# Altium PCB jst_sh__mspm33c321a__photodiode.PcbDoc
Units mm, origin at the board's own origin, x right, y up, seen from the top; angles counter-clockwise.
Board outline 60 x 34 mm, 2 copper layers (Top, Bottom), stack 0 mm thick; 28 components, 13 nets, 108 pads, 50 vias.
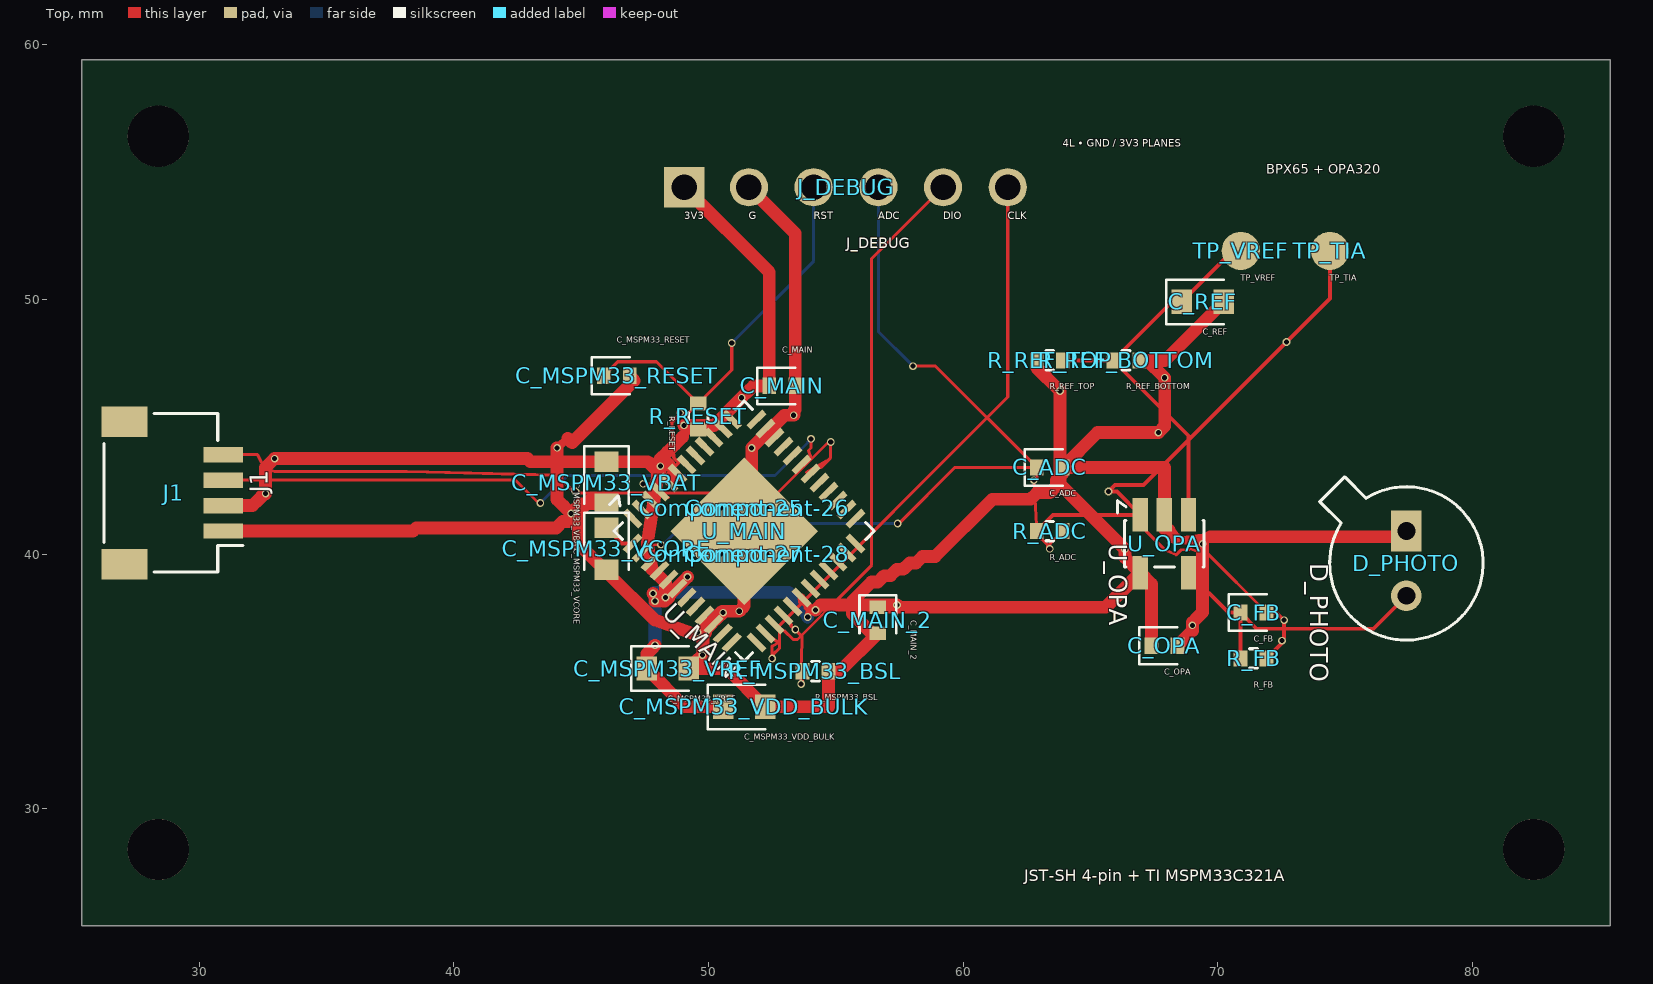
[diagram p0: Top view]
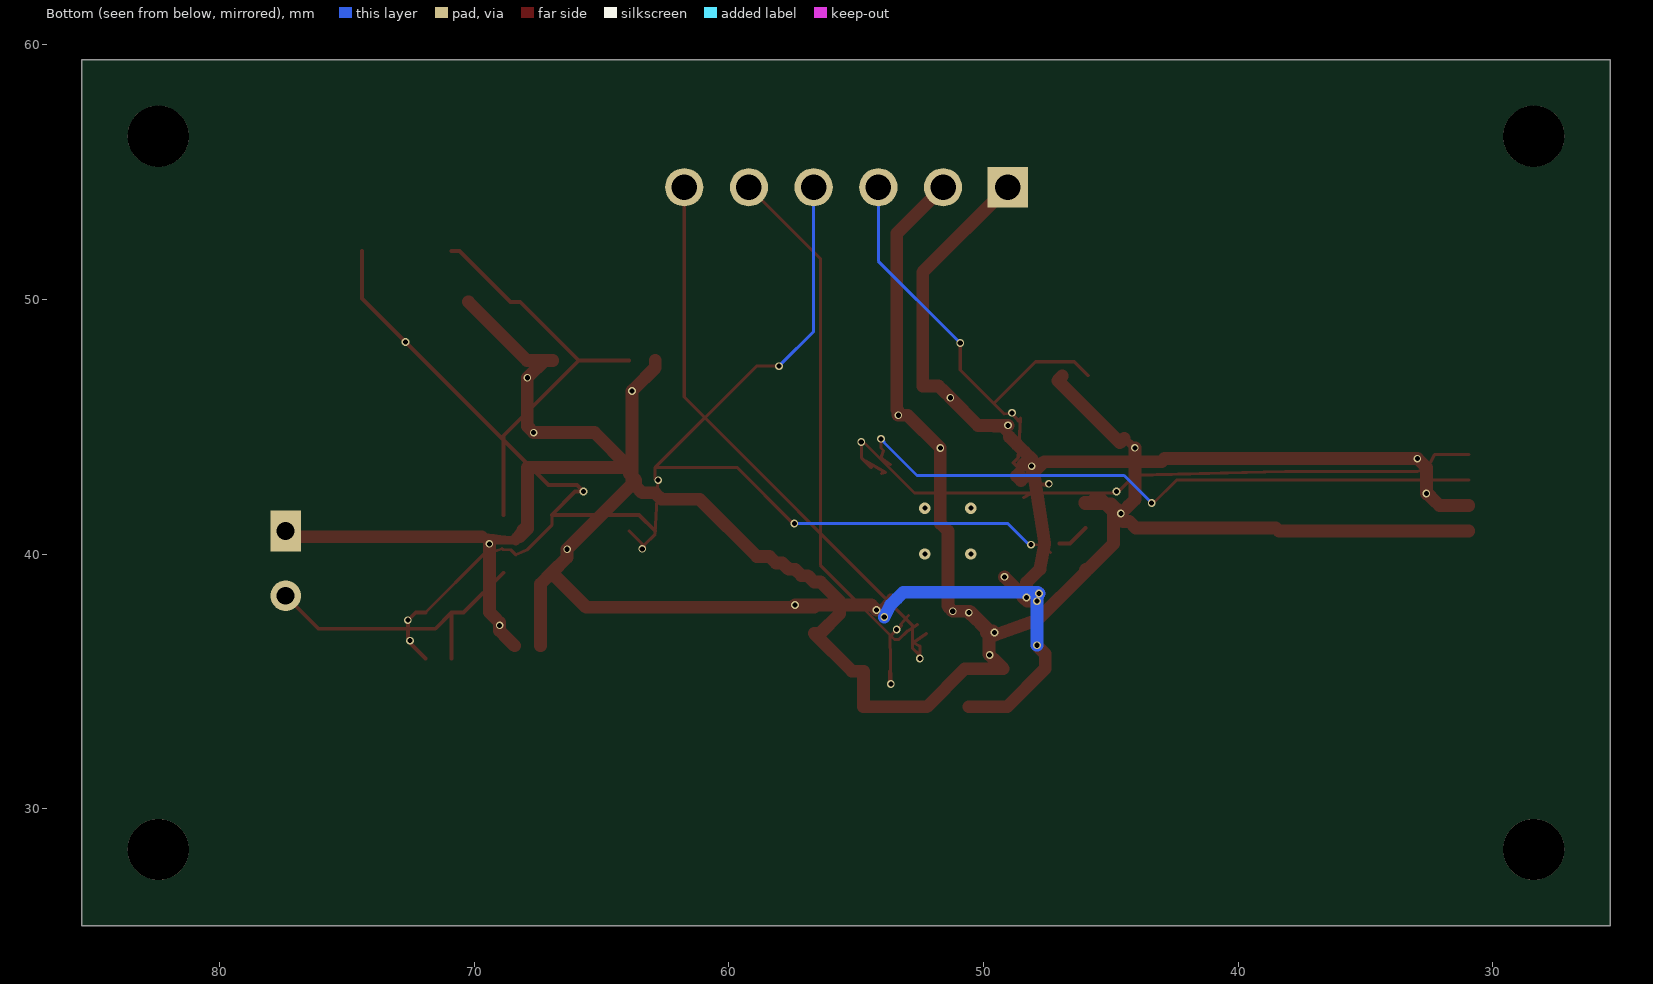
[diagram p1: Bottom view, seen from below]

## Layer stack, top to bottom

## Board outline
25.4,59.4 85.4,59.4 85.4,25.4 25.4,25.4

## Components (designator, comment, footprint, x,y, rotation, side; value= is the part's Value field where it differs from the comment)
C_ADC "" TSCIRCUIT-1.5600x0.6400mm 63.4,43.4 r0 top
C_FB "" TSCIRCUIT-1.5600x0.6400mm 71.4,37.7 r0 top
C_MAIN "" TSCIRCUIT-1.5600x0.6400mm 52.9,46.6 r0 top
C_MAIN_2 "" TSCIRCUIT-0.6400x1.5600mm 56.65,37.4 r270 top
C_MSPM33_RESET "" TSCIRCUIT-1.5600x0.6400mm 46.4,47 r0 top
C_MSPM33_VBAT "" TSCIRCUIT-0.9500x2.4500mm 46,42.8 r270 top
C_MSPM33_VCORE "" TSCIRCUIT-0.9500x2.4500mm 46,40.2 r270 top
C_MSPM33_VDD_BULK "" TSCIRCUIT-2.4500x0.9500mm 51.4,34 r0 top
C_MSPM33_VREF "" TSCIRCUIT-2.4500x0.9500mm 48.4,35.5 r0 top
C_OPA "" TSCIRCUIT-1.5600x0.6400mm 67.9,36.4 r0 top
C_REF "" TSCIRCUIT-2.4500x0.9500mm 69.4,49.9 r0 top
Component-25 "" TSCIRCUIT-0.4500x0.4500mm 50.5,41.8 r0 top
Component-26 "" TSCIRCUIT-0.4500x0.4500mm 52.3,41.8 r0 top
Component-27 "" TSCIRCUIT-0.4500x0.4500mm 50.5,40 r0 top
Component-28 "" TSCIRCUIT-0.4500x0.4500mm 52.3,40 r0 top
D_PHOTO "" TSCIRCUIT-1.2000x3.9400mm 77.4,39.73 r270 top
J1 "" TSCIRCUIT-5.5500x6.8000mm 28.95,42.4 r90 top
J_DEBUG "" TSCIRCUIT-14.2000x1.5000mm 55.4,54.4 r0 top
R_ADC "" TSCIRCUIT-1.5600x0.6400mm 63.4,40.9 r0 top
R_FB "" TSCIRCUIT-1.5600x0.6400mm 71.4,35.9 r0 top
R_MSPM33_BSL "" TSCIRCUIT-1.5600x0.6400mm 54.2,35.4 r0 top
R_REF_BOTTOM "" TSCIRCUIT-1.5600x0.6400mm 66.4,47.6 r0 top
R_REF_TOP "" TSCIRCUIT-1.5600x0.6400mm 63.4,47.6 r0 top
R_RESET "" TSCIRCUIT-0.6400x1.5600mm 49.6,45.4 r270 top
TP_TIA "" TSCIRCUIT-1.5000x1.5000mm 74.4,51.9 r0 top
TP_VREF "" TSCIRCUIT-1.5000x1.5000mm 70.9,51.9 r0 top
U_MAIN "" TSCIRCUIT-9.5459x9.5459mm 51.4,40.9 r315 top
U_OPA "" TSCIRCUIT-2.5000x3.6000mm 67.9,40.4 r270 top

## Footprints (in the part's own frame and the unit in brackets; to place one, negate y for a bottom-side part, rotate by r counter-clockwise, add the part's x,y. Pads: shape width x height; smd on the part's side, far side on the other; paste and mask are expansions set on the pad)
TSCIRCUIT-0.4500x0.4500mm [mm]
TSCIRCUIT-0.6400x1.5600mm [mm]
  rect 0.54x0.64 smd: 1(-0.51,0) 2(0.51,0)
  silkscreen extent -0.98,-0.72 0.51,0.72
TSCIRCUIT-0.9500x2.4500mm [mm]
  rect 0.8x0.95 smd: 1(-0.825,0) 2(0.825,0)
  silkscreen extent -1.42,-0.87 0.82,0.87
TSCIRCUIT-1.2000x3.9400mm [mm]
  rect 1.6x1.2 hole 0.7: 1(-1.17,0)
  round 1.2 hole 0.7: 2(1.37,0)
  silkscreen extent -3.3,-3.4 3.11,3.01
TSCIRCUIT-1.5000x1.5000mm [mm]
  round 1.5 smd: 1(0,0)
TSCIRCUIT-1.5600x0.6400mm [mm]
  rect 0.54x0.64 smd: 1(-0.51,0) 2(0.51,0)
  silkscreen extent -0.98,-0.72 0.51,0.72
TSCIRCUIT-2.4500x0.9500mm [mm]
  rect 0.8x0.95 smd: 1(-0.825,0) 2(0.825,0)
  silkscreen extent -1.42,-0.87 0.83,0.87
TSCIRCUIT-2.5000x3.6000mm [mm]
  rect 1.325x0.6 smd: 1(-1.137,-0.95) 2(-1.137,0) 3(-1.137,0.95) 4(1.138,0.95) 5(1.138,-0.95)
  silkscreen extent -1.69,-1.84 0.91,1.56
TSCIRCUIT-5.5500x6.8000mm [mm]
  rect 1.2x1.8 smd: 1(-2.8,1.875) 1(2.8,1.875)
  rect 0.6x1.55 smd: 1(-1.5,-2) 2(-0.5,-2) 3(0.5,-2) 4(1.5,-2)
  silkscreen extent -3.11,-2.77 3.11,2.69
TSCIRCUIT-9.5459x9.5459mm [mm]
  rect 0.875x0.25 smd: 1(-3.437,-2.75) 2(-3.438,-2.25) 3(-3.438,-1.75) 4(-3.438,-1.25) 5(-3.437,-0.75) 6(-3.438,-0.25) 7(-3.438,0.25) 8(-3.438,0.75) 9(-3.437,1.25) 10(-3.438,1.75) 11(-3.438,2.25) 12(-3.438,2.75) 25(3.438,2.75) 26(3.438,2.25) 27(3.438,1.75) 28(3.438,1.25) 29(3.438,0.75) 30(3.438,0.25) 31(3.438,-0.25) 32(3.438,-0.75) 33(3.438,-1.25) 34(3.438,-1.75) 35(3.438,-2.25) 36(3.438,-2.75)
  rect 0.25x0.875 smd: 13(-2.75,3.438) 14(-2.25,3.438) 15(-1.75,3.438) 16(-1.25,3.438) 17(-0.75,3.438) 18(-0.25,3.438) 19(0.25,3.438) 20(0.75,3.438) 21(1.25,3.438) 22(1.75,3.438) 23(2.25,3.438) 24(2.75,3.438) 37(2.75,-3.438) 38(2.25,-3.437) 39(1.75,-3.437) 40(1.25,-3.437) 41(0.75,-3.438) 42(0.25,-3.437) 43(-0.25,-3.437) 44(-0.75,-3.437) 45(-1.25,-3.438) 46(-1.75,-3.437) 47(-2.25,-3.437) 48(-2.75,-3.437)
  rect 4.1x4.1 smd: 49(0,0)
  silkscreen extent -4.47,-3.61 3.61,3.61
TSCIRCUIT-14.2000x1.5000mm [mm]
  rect 1.6x1.6 hole 1: 1(-6.35,0)
  round 1.5 hole 1: 2(-3.81,0) 3(-1.27,0) 4(1.27,0) 5(3.81,0) 6(6.35,0)

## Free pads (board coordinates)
  round 2.4 hole 2.4 unplated: NPTH-1(28.4,28.4) NPTH-2(82.4,56.4) NPTH-3(82.4,28.4) NPTH-4(28.4,56.4)

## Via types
v1: diameter 0.3, hole 0.2, Top to Bottom, 46 vias
v2: diameter 0.45, hole 0.2, Top to Bottom, 4 vias

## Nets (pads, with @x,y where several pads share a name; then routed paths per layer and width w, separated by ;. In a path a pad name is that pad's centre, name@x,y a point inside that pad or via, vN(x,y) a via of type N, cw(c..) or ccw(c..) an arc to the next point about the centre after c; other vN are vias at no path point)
ADC_IN: C_ADC.1 J_DEBUG.4 R_ADC.2 U_MAIN.47 | length 35.4
  Top w0.12: U_MAIN.47 47.673,40.355 v1(48.138,40.369) ; v1(57.428,41.2) 57.48,41.252 57.53,41.252 59.678,43.4 C_ADC.1 ; v1(58.031,47.377) 58.913,47.377 C_ADC.1 ; R_ADC.2 63.4,40.39 v1(63.4,40.2) 63.321,40.279 63.321,40.352 62.894,40.779 v1(62.775,42.9) 62.89,42.928 62.89,43.15 C_ADC.1
  Bottom w0.12: v1(48.138,40.369) 48.171,40.388 48.238,40.388 49.051,41.2 v1(57.428,41.2) ; J_DEBUG.4 56.67,48.738 57.961,47.447 v1(58.031,47.377)
GND: C_ADC.2 C_MAIN.2 C_MAIN_2.2 C_MSPM33_RESET.2 C_MSPM33_VBAT.2 C_MSPM33_VCORE.2 C_MSPM33_VDD_BULK.2 C_MSPM33_VREF.2 C_OPA.2 C_REF.2 D_PHOTO.1 J1.1@30.95,40.9 J_DEBUG.2 R_MSPM33_BSL.2 R_REF_BOTTOM.2 U_MAIN.39 U_MAIN.49 U_OPA.2 | length 116.2
  Top w0.12: U_MAIN.39 v1(50.575,37.7)
  Top w0.25: 49.897,36.923 U_MAIN.39 49.897,36.923
  Top w0.312: v1(44.057,44.168) v1@44.09,44.196 ; U_OPA.2@67.9,41.248 68.151,40.997 68.369,40.681 68.525,40.525 69.275,40.525 v1(69.4,40.4) ; 68.369,40.525 68.815,40.576 69.262,40.626
  Top w0.325: v1@44.09,44.196 44.122,44.196 44.471,44.545 ; v1(49.571,36.917) 49.892,36.917 49.897,36.923 ; 69.262,40.626 69.709,40.677
  Top w0.375: 68.215,40.677 68.369,40.525
  Top w0.5: J1.1@30.95,40.9 31.442,40.9 31.933,40.9 32.425,40.9 32.917,40.9 33.408,40.9 33.9,40.9 34.392,40.9 34.884,40.9 35.375,40.9 35.867,40.9 36.359,40.9 36.85,40.9 37.342,40.9 37.834,40.9 38.325,40.9 38.4,40.9 38.525,41.025 44.025,41.025 44.275,41.275 44.525,41.275 45.275,42.025 46.025,42.025 46.025,42 C_MSPM33_VBAT.2 ; v1(44.057,44.168) 44.057,43.763 44.057,43.358 44.057,42.954 44.057,42.549 44.057,42.144 44.315,41.887 44.573,41.629 v1(44.609,41.593) 44.8,41.784 44.991,41.975 45.327,41.975 45.664,41.975 C_MSPM33_VBAT.2 ; 44.471,44.545 44.648,44.368 47.087,46.807 46.91,46.984 C_MSPM33_RESET.2 ; v1(49.571,36.917) 49.643,36.989 49.775,36.989 50.029,37.243 50.283,37.497 50.537,37.751 50.872,37.751 v1(51.208,37.751) 51.353,37.896 51.353,37.92 51.4,37.967 51.4,38.456 51.4,38.945 51.4,39.433 51.4,39.922 51.4,40.411 U_MAIN.49 51.696,41.196 v1(51.696,44.162) 52.98,45.446 v1(53.345,45.446) 53.36,45.461 53.36,45.621 53.41,45.67 C_MAIN.2 53.41,52.58 J_DEBUG.2 ; 49.897,36.923 49.775,36.8 49.6,36.8 47.9,37.4 46,39.3 C_MSPM33_VCORE.2 45.975,39.4 45.9,39.4 44.9,40.4 44.9,41.65 45.4,42.15 45.65,42.15 45.825,41.975 C_MSPM33_VBAT.2 ; v1(50.575,37.7) 50.127,37.273 49.826,36.965 49.787,36.972 49.787,36.517 49.787,36.062 v1(49.762,36.037) 49.493,35.768 C_MSPM33_VREF.2 50.725,35.5 C_MSPM33_VDD_BULK.2 54.71,34 R_MSPM33_BSL.2 55.16,35.4 C_MAIN_2.2 56.41,36.89 55.65,37.65 55.65,38.15 56.4,38.9 56.65,38.9 56.9,39.15 57.15,39.15 57.4,39.4 57.65,39.4 57.9,39.65 58.15,39.65 58.4,39.9 58.9,39.9 61.15,42.15 62.65,42.15 62.9,42.4 63.4,42.4 63.65,42.65 63.65,42.9 63.9,43.15 63.9,43.4 C_ADC.2 ; U_OPA.2@67.9,41.248 U_OPA.2 ; 68.215,40.677 67.9,40.992 U_OPA.2 ; C_OPA.2 68.705,36.695 69,36.99 v1(69,37.2) 69.004,37.204 69.004,37.316 69.202,37.514 69.4,37.712 69.4,38.16 69.4,38.608 69.4,39.056 69.4,39.504 69.4,39.952 v1(69.4,40.4) ; 69.709,40.677 70.206,40.677 70.704,40.677 71.202,40.677 71.7,40.677 72.198,40.677 72.696,40.677 73.194,40.677 73.692,40.677 74.189,40.677 74.687,40.677 75.185,40.677 75.683,40.677 76.181,40.677 76.679,40.677 77.177,40.677 D_PHOTO.1 ; C_REF.2 67.925,47.6 R_REF_BOTTOM.2 67.23,47.6 67.887,46.943 v1(67.91,46.92) 67.91,45.015 67.668,44.773 v1(67.662,44.767) 65.277,44.767 C_ADC.2 ; C_ADC.2 67.9,43.4 U_OPA.2
MAIN_RESET: C_MSPM33_RESET.1 J_DEBUG.3 R_RESET.1 U_MAIN.4 | length 21.7
  Top w0.12: C_MSPM33_RESET.1 46.437,47.547 46.528,47.547 47.963,47.547 R_RESET.1 ; U_MAIN.4 48.424,42.213 47.918,42.484 47.79,42.751 47.511,42.668 v1(47.438,42.756) 47.997,42.741 48.839,43.582 48.638,43.783 48.542,45.338 48.638,45.225 48.638,45.257 48.79,45.409 48.797,45.409 v1(48.882,45.54) 49.195,45.505 R_RESET.1 ; v1(50.914,48.286) 50.914,47.224 R_RESET.1
  Bottom w0.12: v1(50.914,48.286) 51.052,48.424 51.056,48.424 54.13,51.498 J_DEBUG.3
MSPM33_BSL_INVOKE: R_MSPM33_BSL.1 U_MAIN.33 | length 3.6
  Top w0.12: U_MAIN.33 53.25,37.228 53.229,37.186 53.38,37.034 v1(53.414,37.034) 53.431,37.017 53.431,37.001 53.677,36.755 v1(53.636,34.894) 53.649,34.882 53.649,34.917 53.69,34.957 R_MSPM33_BSL.1
MSPM33_SWCLK: J_DEBUG.6 U_MAIN.35 | length 23.7
  Top w0.12: U_MAIN.35 52.756,36.526 52.504,36.379 52.5,36.375 v1(52.5,35.9) 52.548,35.948 52.548,36.062 52.795,36.308 52.795,37.209 61.75,46.164 J_DEBUG.6
MSPM33_SWDIO: J_DEBUG.5 U_MAIN.34 | length 21.2
  Top w0.12: U_MAIN.34 52.98,36.973 52.991,36.979 52.999,36.971 53.325,36.645 53.347,36.645 53.492,36.645 56.408,39.561 56.408,51.598 J_DEBUG.5
MSPM33_VCORE: C_MSPM33_VCORE.1 U_MAIN.48 | length 1.3
  Top w0.15: C_MSPM33_VCORE.1 46.611,40.414 U_MAIN.48
PD_SUM: C_FB.1 D_PHOTO.2 R_FB.1 U_OPA.4 | length 11.8
  Top w0.15: U_OPA.4 70.412,37.7 C_FB.1 ; R_FB.1 C_FB.1 ; D_PHOTO.2 76.107,37.066 71.627,37.064 71.523,37.067 C_FB.1
TIA_OUT: C_FB.2 R_ADC.1 R_FB.2 TP_TIA.1 U_OPA.1 | length 29.2
  Top w0.12: U_OPA.1 66.95,41.131 67.9,40.181 68.36,39.97 68.54,40.15 68.88,40.181 68.906,40.205 69.163,40.121 69.413,40.038 69.359,40.014 69.596,40.014 C_FB.2
  Top w0.15: R_ADC.1 63.528,41.537 U_OPA.1 66.034,42.453 v1(65.703,42.453) 65.785,42.535 65.785,42.537 65.962,42.713 67.084,42.713 v1(72.696,48.325) 72.718,48.347 74.4,50.029 TP_TIA.1 ; R_FB.2 72.516,36.506 v1(72.516,36.601) 72.557,36.642 72.557,36.669 72.6,36.713 v1(72.6,37.404) 72.56,37.44 72.552,37.44 72.292,37.7 C_FB.2
UART_MAIN_RX: J1.4 U_MAIN.19 | length 28
  Top w0.12: J1.4 32.295,43.9 32.625,43.266 32.735,43.311 32.962,43.233 38.174,43.233 44.06,43.091 44.628,42.523 44.711,42.523 v1(44.782,42.452) 44.838,42.396 52.709,42.396 54.653,44.34 54.74,44.34 v1(54.8,44.4) 54.8,43.78 54.428,43.409 54.426,43.406 54.406,43.393 54.624,43.649 53.844,43.2 U_MAIN.19
UART_MAIN_TX: J1.3 U_MAIN.18 | length 25.8
  Top w0.12: J1.3 42.426,42.9 43.326,42 v1(43.4,42) ; U_MAIN.18 54.032,43.773 53.93,44.066 54.026,44.162 v1(54.026,44.523)
  Bottom w0.12: v1(43.4,42) 44.48,43.081 52.45,43.081 52.609,43.08 53.91,44.381 53.91,44.407 v1(54.026,44.523)
VCC_3V3: C_MAIN.1 C_MAIN_2.1 C_MSPM33_VBAT.1 C_MSPM33_VDD_BULK.1 C_MSPM33_VREF.1 C_OPA.1 J1.2 J_DEBUG.1 R_REF_TOP.1 R_RESET.2 U_MAIN.5 U_MAIN.6 U_MAIN.31 U_MAIN.43 U_OPA.5 | length 90.3
  Top w0.12: U_MAIN.43 v1(49.175,39.1)
  Top w0.2: U_MAIN.31 54.146,37.8 v1(54.2,37.8) ; U_MAIN.31@53.875,37.895 53.903,37.895 v1(53.9,37.525)
  Top w0.25: 48.483,38.337 U_MAIN.43 U_MAIN.43@48.793,38.648 ; U_MAIN.6@48.483,43.463 U_MAIN.6 48.704,43.066 ; 48.527,42.889 U_MAIN.5 ; 48.978,44.594 49.274,44.89 R_RESET.2 49.441,45.049 v1(49.04,45.049) ; U_MAIN.5 48.164,43.075 48.13,43.11 U_MAIN.5
  Top w0.267: U_MAIN.43@48.476,38.344 U_MAIN.43@48.793,38.648
  Top w0.275: U_MAIN.31@53.87,37.989 53.876,37.9 U_MAIN.31@53.875,37.895
  Top w0.3: U_MAIN.31 53.661,38.126 53.745,38.11 53.837,38.063 U_MAIN.31@53.87,37.989
  Top w0.45: v1@48.3,38.2 v1(48.313,38.29)
  Top w0.5: J1.2 31.332,41.9 31.714,41.9 32.096,41.9 32.31,42.113 32.523,42.327 32.565,42.327 v1(32.613,42.375) 32.613,43.392 v1(32.966,43.745) 42.897,43.745 42.899,43.743 43.017,43.625 C_MSPM33_VBAT.1 46.404,43.625 46.807,43.625 47.211,43.625 47.614,43.625 47.889,43.35 48.13,43.11 48.112,43.127 v1(48.112,43.45) 48,43.338 48,43 47.6,40.4 47.787,39.406 48.313,38.88 v1(48.313,38.29) ; v1(47.824,38.452) 48.025,38.15 48.275,38.15 48.476,38.344 ; v1(47.9,38.15) 48.225,38.15 v1(49.175,39.1) ; v1(47.904,36.416) 47.851,36.363 47.851,36.356 47.575,36.08 47.575,35.79 C_MSPM33_VREF.1 49.075,34 C_MSPM33_VDD_BULK.1 ; v1@48.3,38.2 48.346,38.2 48.483,38.337 ; 48.483,43.463 48.24,43.706 48.09,43.706 48.386,44.002 48.682,44.298 48.978,44.594 ; 48.527,42.889 48.704,43.066 ; v1(49.04,45.049) 50.214,45.049 v1(51.301,46.136) 51.323,46.158 51.544,46.379 51.765,46.6 52.078,46.6 C_MAIN.1 52.39,51.06 J_DEBUG.1 ; v1(54.2,37.8) 54.4,38 v1(57.4,38) 57.363,38 57.273,37.91 56.961,37.91 C_MAIN_2.1 65.598,37.91 ; R_REF_TOP.1 62.89,47.31 63.745,46.455 v1(63.8,46.4) 63.8,42.737 v1(66.349,40.188) 66.349,39.863 U_OPA.5 ; 65.598,37.911 U_OPA.5 ; C_OPA.1 67.39,38.823 U_OPA.5
  Bottom w0.5: v1(47.824,38.452) 47.875,38.504 47.975,38.504 48.445,38.504 48.915,38.504 49.384,38.504 49.854,38.504 50.324,38.504 50.794,38.504 51.264,38.504 51.734,38.504 52.204,38.504 52.674,38.504 53.143,38.504 53.397,38.25 53.65,37.997 v1(53.9,37.525) ; v1(47.9,38.15) 47.872,38.404 47.872,38.4 47.904,38.368 47.904,37.88 47.904,37.392 47.904,36.904 v1(47.904,36.416)
VREF_0V5: C_REF.1 R_REF_BOTTOM.1 R_REF_TOP.2 TP_VREF.1 U_OPA.3 | length 16.1
  Top w0.15: R_REF_TOP.2 R_REF_BOTTOM.1 ; U_OPA.3 68.85,44.64 R_REF_BOTTOM.1 ; TP_VREF.1 70.575,51.9 C_REF.1 68.19,49.9 R_REF_BOTTOM.1
pads on no net: J1.1@27.075,39.6 J1.1@27.075,45.2 U_MAIN.1 U_MAIN.2 U_MAIN.3 U_MAIN.7 U_MAIN.8 U_MAIN.9 U_MAIN.10 U_MAIN.11 U_MAIN.12 U_MAIN.13 U_MAIN.14 U_MAIN.15 U_MAIN.16 U_MAIN.17 U_MAIN.20 U_MAIN.21 U_MAIN.22 U_MAIN.23 U_MAIN.24 U_MAIN.25 U_MAIN.26 U_MAIN.27 U_MAIN.28 U_MAIN.29 U_MAIN.30 U_MAIN.32 U_MAIN.36 U_MAIN.37 U_MAIN.38 U_MAIN.40 U_MAIN.41 U_MAIN.42 U_MAIN.44 U_MAIN.45 U_MAIN.46
copper on no net:
  other v2: 50.5,40 52.3,40 50.5,41.8 52.3,41.8

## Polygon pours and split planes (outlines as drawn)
GND on Mid1 (solid): 85.1,59.1 25.7,59.1 25.7,25.7 85.1,25.7
VCC_3V3 on Mid2 (solid): 85.1,59.1 25.7,59.1 25.7,25.7 85.1,25.7

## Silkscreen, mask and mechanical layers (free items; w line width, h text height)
Top Overlay:
  text "4L • GND / 3V3 PLANES" at 63.9,55.9 h0.48
  text "BPX65 + OPA320" at 71.9,54.8 h0.65
  text "JST-SH 4-pin + TI MSPM33C321A" at 62.4,27 h0.78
